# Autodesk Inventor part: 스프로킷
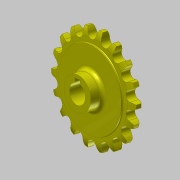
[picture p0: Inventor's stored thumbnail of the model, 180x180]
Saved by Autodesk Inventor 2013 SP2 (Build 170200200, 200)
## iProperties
Created: 2016-03
Part Number: 스프로킷
Material: 강철, 탄소
Document SubType Name: Modeling
Designer: mduedu
Density: 7.87 g/cm^3
Mass: 301.818 g
Surface Area: 124.882 cm^2
Volume: 38.3505 cm^3
Author: mduedu
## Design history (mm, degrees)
sketch "스케치1"
  geometry: L1 (0, 5)-(29.5, 5); L2 (29.5, 5)-(29.5, 4.1); L3 (30, 3.6)-(33.625, 3.6); L4 (40, 2)-(40, 0); L5 (40, 0)-(0, 0); L6 (0, 0)-(0, 5); L7 (0, -5)-(29.5, -5); L8 (29.5, -5)-(29.5, -4.1); L9 (30, -3.6)-(33.625, -3.6); L10 (40, -2)-(40, 0); L11 (0, 0)-(0, -5); A1 r 13.5 centre (33.625, -9.9) between (40, 2) and (33.625, 3.6); A2 r 13.5 centre (33.625, 9.9) between (33.625, -3.6) and (40, -2); A3 r 0.5 centre (30, 4.1) between (29.5, 4.1) and (30, 3.6); A4 r 0.5 centre (30, -4.1) between (30, -3.6) and (29.5, -4.1); 2 further points
  constraints: 22 end point, 8 point on circle, 6 symmetric about line, 5 tangent, 4 centre point, 4 parallel, 4 point on line, 1 equal radius, 1 horizontal, 1 perpendicular, 1 other
  dimensions: "d0" = 80 diameter of L4 L6; "d2" = 59 diameter of L2 L6; "d3" = 1.6 vertical distance of L4.start L3.end; "d4" = 3.6 distance from line of L4.end L3; "d5" = 5 distance between parallel lines of L5 L1; "d6" = 13.5 radius of A1; "d15" = 0.5 radius of A3
revolve "회전1" sketch "스케치1" stored, may be unused: angle "d7" = 90 deg
sketch "스케치2" dims "d8" = 65.2, "d11" = 80
  geometry: L1 (0, 0)-(0, 32.6); A1 r 36.57 centre (0, 0) between (-16.231, 32.771) and (0, 36.57); A2 r 3.97 centre (0, 36.57) between (-3.866, 35.665) and (0, 32.6); A3 r 12.7 centre (-16.231, 32.771) between (-3.866, 35.665) and (-5.534, 39.615); A4 r 12.7 centre (16.231, 32.771) between (5.534, 39.615) and (3.866, 35.665); A5 r 3.97 centre (0, 36.57) between (0, 32.6) and (3.866, 35.665); A6 r 40 centre (0, 0) between (5.534, 39.615) and (-5.534, 39.615); 2 further points
  constraints: 12 point on circle, 6 centre point, 4 coincident, 3 symmetric about line, 2 end point, 1 point on line, 1 tangent, 1 vertical, 1 vertical alignment, 7 other
  dimensions: "d10" = 73.14 diameter of A1; "d12" = 12.7 radius of A3
extrude "돌출1" cut sketch "스케치2" stored distance "d13" = 10; taper "d14" = 0 deg
sketch "스케치3"
  geometry: C1 r 12.5 at (0, 0); 1 further point
  constraints: 1 centre point, 1 coincident
  dimensions: "d19" = 25 diameter of C1
extrude "돌출2" join sketch "스케치3" distance "d20" = 10; taper "d21" = 0 deg
fillet "모깎기1" dims "d22" = 3
sketch "스케치4"
  geometry: L1 (-2.5, 0)-(2.5, 0); L2 (2.5, 0)-(2.5, 9.8); L3 (2.5, 9.8)-(-2.5, 9.8); L4 (-2.5, 9.8)-(-2.5, 0); C1 r 7.5 at (0, 0); 2 further points
  constraints: 8 end point, 2 coincident, 2 parallel, 1 centre point, 1 horizontal, 1 midpoint, 1 perpendicular
  dimensions: "d23" = 15 diameter of C1; "d25" = 5 distance of L2.end L3.end; "d26" = 9.8 distance of L1.end L2.end
extrude "돌출3" cut sketch "스케치4" stored distance "d27" = 8; taper "d28" = 0 deg
node "솔리드1"
pattern_circular "원형 패턴1" dims angle "d17" = 360 deg
